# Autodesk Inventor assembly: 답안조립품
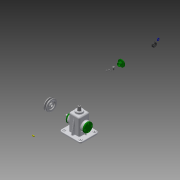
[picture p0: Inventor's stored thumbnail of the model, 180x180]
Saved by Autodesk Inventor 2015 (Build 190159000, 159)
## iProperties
Created: 2016-02
Part Number: 답안조립품
Document SubType Name: Assembly
Designer: Administrator
Author: Administrator
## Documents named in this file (19)
- C:\Users\Administrator\Desktop\460219V1011\답안조립품.iam
- C:\Users\Administrator\Desktop\460219V1011\본체.ipt
- C:\Users\Administrator\Desktop\460219V1011\V-벨트풀리.ipt
- C:\Users\Administrator\Desktop\460219V1011\고정핀.ipt
- C:\Users\Administrator\Desktop\460219V1011\뒤커버.ipt
- C:\Users\Administrator\Desktop\460219V1011\링크.ipt
- C:\Users\Administrator\Desktop\460219V1011\멈춤링 6 x 5.ipt
- C:\Users\Administrator\Desktop\460219V1011\멈춤링 15 x 1.ipt
- C:\Users\Administrator\Desktop\460219V1011\베어링 15 x 35 x 11.ipt
- C:\Users\Administrator\Desktop\460219V1011\볼트 M3 x 8.ipt
- C:\Users\Administrator\Desktop\460219V1011\볼트 M4 x 10.ipt
- C:\Users\Administrator\Desktop\460219V1011\볼트 M6 x 12.ipt
- C:\Users\Administrator\Desktop\460219V1011\상부부시.ipt
- C:\Users\Administrator\Desktop\460219V1011\슬라이드바.ipt
- C:\Users\Administrator\Desktop\460219V1011\앞커버.ipt
- C:\Users\Administrator\Desktop\460219V1011\오일실 15 25 7.ipt
- C:\Users\Administrator\Desktop\460219V1011\와셔.ipt
- C:\Users\Administrator\Desktop\460219V1011\키 5 x 5 x 14.ipt
- C:\Users\Administrator\Desktop\460219V1011\편심축.ipt
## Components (5 placed, 5 different names)
1. V-벨트풀리:1
2. 고정핀:1
3. ISO 4762 M3 x 8:1
4. ISO 4762 M4 x 10:1
5. ISO 4018 M6 x 12:1
